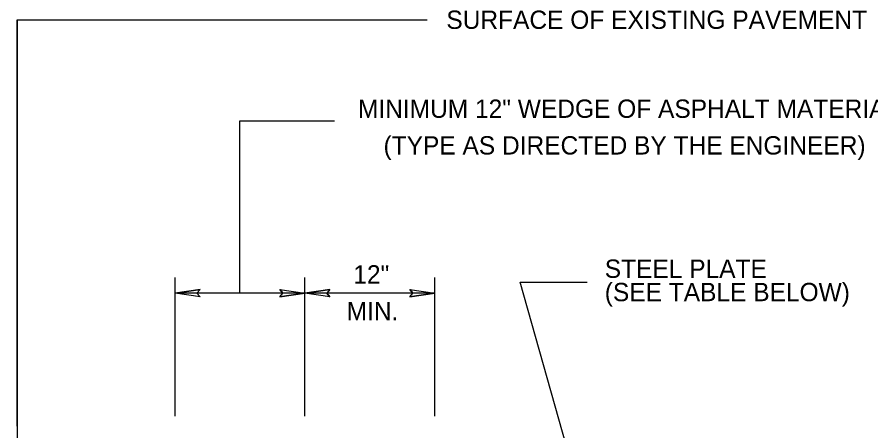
# Model space of a CAD drawing. Extents: x 12.5 to 19.6, y 6 to 16.
# Drawn here: x 13.667 to 16.462, y 13.061 to 14.416 of the extents above; entities that cross this region are included whole.
import ezdxf

# ---------------------------------------------------------------- set-up
doc = ezdxf.new("R2010")
doc.units = 0
for name, color, linetype in [('DETL-DIMS', 7, 'Continuous'), ('DETL-NOTE', 7, 'Continuous'), ('ROAD-EDGE', 7, 'Continuous')]:
    doc.layers.add(name, color=color, linetype=linetype)

msp = doc.modelspace()

# ---------------------------------------------------------------- linework, layer by layer
at = {"layer": 'DETL-DIMS'}
for p, q in [((13.6668, 14.4071), (13.6668, 12.9112)), ((14.1839, 13.1095), (14.1839, 13.5629)), ((14.6089, 13.1095), (14.6089, 13.5629)), ((15.0339, 13.1095), (15.0339, 13.5629)), ((14.2657, 13.5238), (14.1839, 13.5119)), ((14.6089, 13.5119), (14.1839, 13.5119)), ((14.2657, 13.5), (14.1839, 13.5119)), ((14.2657, 13.5238), (14.2556, 13.5119)), ((14.2657, 13.5), (14.2556, 13.5119)), ((14.5271, 13.5238), (14.6089, 13.5119)), ((14.5271, 13.5238), (14.5373, 13.5119)), ((14.5271, 13.5), (14.6089, 13.5119)), ((14.5271, 13.5), (14.5373, 13.5119)), ((14.6907, 13.5238), (14.6089, 13.5119)), ((15.0339, 13.5119), (14.6089, 13.5119)), ((14.6907, 13.5), (14.6089, 13.5119)), ((14.6907, 13.5238), (14.6806, 13.5119)), ((14.6907, 13.5), (14.6806, 13.5119)), ((14.9521, 13.5238), (15.0339, 13.5119)), ((14.9521, 13.5238), (14.9623, 13.5119)), ((14.9521, 13.5), (15.0339, 13.5119)), ((14.9521, 13.5), (14.9623, 13.5119))]:
    msp.add_line(p, q, dxfattribs=at)
for points in [[(13.6668, 13.0764), (13.6668, 14.4071), (15.0092, 14.4071)], [(14.3964, 13.5119), (14.3962, 14.0767), (14.7065, 14.0767)], [(15.4782, 12.964), (15.3133, 13.5481), (15.5331, 13.5481)]]:
    msp.add_lwpolyline(points, dxfattribs=at)
for points in [[(14.2657, 13.5), (14.1839, 13.5119), (14.2657, 13.5238), (14.2556, 13.5119)], [(14.5271, 13.5238), (14.6089, 13.5119), (14.5271, 13.5), (14.5373, 13.5119)], [(14.6907, 13.5), (14.6089, 13.5119), (14.6907, 13.5238), (14.6806, 13.5119)], [(14.9521, 13.5238), (15.0339, 13.5119), (14.9521, 13.5), (14.9623, 13.5119)]]:
    msp.add_lwpolyline(points, close=True, dxfattribs=at)
at = {"layer": 'ROAD-EDGE'}
msp.add_line((14.6089, 13.1095), (14.6089, 13.5629), dxfattribs=at)

# ---------------------------------------------------------------- texts
at = {"layer": 'DETL-NOTE'}
for s, p in [('SURFACE OF EXISTING PAVEMENT', (15.0721, 14.3771)), ('MINIMUM 12" WEDGE OF ASPHALT MATERIAL', (14.7827, 14.0859)), ('(TYPE AS DIRECTED BY THE ENGINEER)', (14.8664, 13.9659)), ('STEEL PLATE', (15.5907, 13.5622)), ('12"', (14.7676, 13.5437)), ('(SEE TABLE BELOW)', (15.5907, 13.4858)), ('MIN.', (14.7456, 13.4237))]:
    msp.add_text(s, height=0.06, dxfattribs=at).set_placement(p)

doc.saveas('drawing.dxf')
